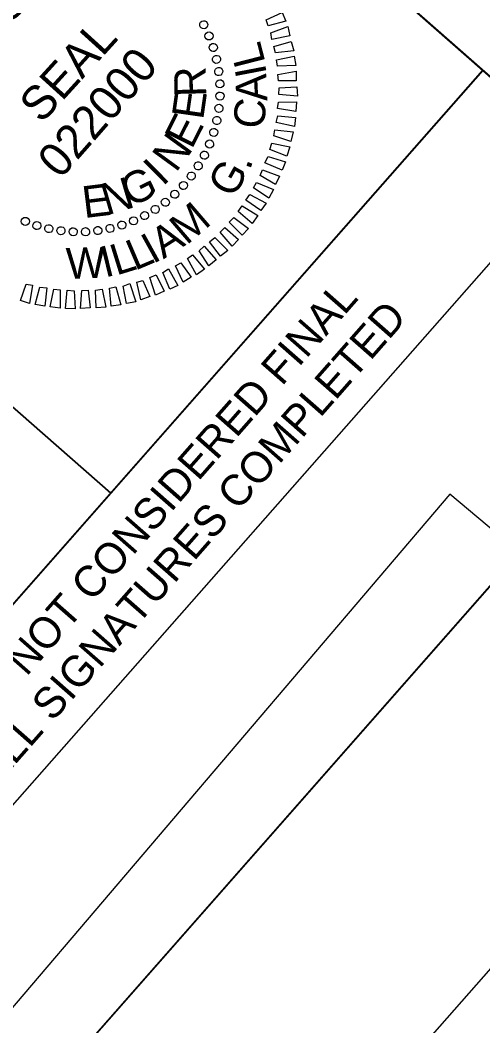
# Model space of a CAD drawing. Extents: x 2189835 to 2191772, y 387461 to 389531.
# Drawn here: x 2190982.4 to 2191064.5, y 389152 to 389330.6 of the extents above; entities that cross this region are included whole.
import ezdxf

# ---------------------------------------------------------------- set-up
doc = ezdxf.new("R2010")
doc.units = 0
for name, color, linetype in [('Sheet Clip Boundary CELL', 7, 'Continuous'), ('Sheet Layout Plan Border', 7, 'Continuous'), ('Sheet Plan CELL', 7, 'Continuous'), ('Sheet Plan Layout CELL', 7, 'Continuous'), ('Sheet Professional Seal CELL', 7, 'Continuous'), ('Sheet Sticker Exception Certification CELL', 7, 'Continuous')]:
    doc.layers.add(name, color=color, linetype=linetype)

msp = doc.modelspace()

# ---------------------------------------------------------------- linework, layer by layer
at = {"layer": 'Sheet Clip Boundary CELL'}
msp.add_lwpolyline([(2190233.88, 388250.3), (2190718.45, 387881.26), (2190850.4, 387777.99), (2191678.63, 388725.5), (2191058.62, 389246.4), (2190957.74, 389128.02), (2190818.15, 389247.91), (2190051.03, 388378.47)], close=True, dxfattribs=at)
at = {"layer": 'Sheet Layout Plan Border'}
msp.add_lwpolyline([(2190847.19, 387643.49), (2191771.58, 388694.94), (2191141.84, 389248.59), (2191016.87, 389106.45), (2190858.04, 389246.09), (2190058.62, 388336.78)], close=True, dxfattribs=at)
at = {"layer": 'Sheet Plan CELL'}
msp.add_line((2190913.95, 389320.85), (2190998.42, 389246.61), dxfattribs=at)
for points in [[(2190951.79, 389420.78), (2189961.36, 388294.21), (2190749.93, 387600.92), (2191740.35, 388727.47)], [(2190913.95, 389320.85), (2190979.96, 389395.96), (2191064.47, 389321.68), (2190998.45, 389246.57)], [(2190749.93, 387600.92), (2189961.36, 388294.17), (2190819.67, 389270.52), (2190932.38, 389171.45), (2191064.47, 389321.68), (2191740.35, 388727.47)], [(2190847.89, 389245.71), (2190913.95, 389320.85), (2190998.45, 389246.57), (2190932.38, 389171.45)]]:
    msp.add_lwpolyline(points, close=True, dxfattribs=at)
at = {"layer": 'Sheet Plan Layout CELL'}
for points in [[(2190952.63, 389101.43), (2191110.61, 389281.13), (2190951.8, 389420.79), (2190793.79, 389241.07)], [(2189961.36, 388294.17), (2190749.93, 387600.92), (2191740.34, 388727.46), (2191110.6, 389281.11), (2190952.63, 389101.43), (2190793.79, 389241.07)]]:
    msp.add_lwpolyline(points, close=True, dxfattribs=at)
at = {"layer": 'Sheet Professional Seal CELL'}
for p, q in [((2191014.97, 389329.79), (2191014.97, 389329.79)), ((2191015.89, 389327.79), (2191015.89, 389327.79)), ((2191016.69, 389325.75), (2191016.69, 389325.75)), ((2191017.23, 389323.63), (2191017.23, 389323.63)), ((2191017.65, 389321.46), (2191017.65, 389321.46)), ((2190992.76, 389318.07), (2190992.76, 389318.07)), ((2191017.83, 389319.31), (2191017.83, 389319.31)), ((2191017.87, 389317.08), (2191017.87, 389317.08)), ((2191017.66, 389314.94), (2191017.66, 389314.94)), ((2191017.28, 389312.75), (2191017.28, 389312.75)), ((2191016.74, 389310.63), (2191016.74, 389310.63)), ((2191016.03, 389308.6), (2191016.03, 389308.6)), ((2191015.1, 389306.62), (2191015.1, 389306.62)), ((2191013.95, 389304.7), (2191013.95, 389304.7)), ((2191012.76, 389302.89), (2191012.76, 389302.89)), ((2191011.35, 389301.2), (2191011.35, 389301.2)), ((2191009.78, 389299.64), (2191009.78, 389299.64)), ((2191006.38, 389296.97), (2191006.38, 389296.97)), ((2191008.1, 389298.25), (2191008.1, 389298.25)), ((2190983.28, 389294.8), (2190983.28, 389294.8)), ((2191002.48, 389294.94), (2191002.48, 389294.94)), ((2191004.47, 389295.85), (2191004.47, 389295.85)), ((2190985.31, 389294.08), (2190985.31, 389294.08)), ((2190987.44, 389293.55), (2190987.44, 389293.55)), ((2190989.63, 389293.16), (2190989.63, 389293.16)), ((2190991.77, 389292.95), (2190991.77, 389292.95)), ((2190994, 389292.99), (2190994, 389292.99)), ((2190996.15, 389293.17), (2190996.15, 389293.17)), ((2190998.32, 389293.6), (2190998.32, 389293.6)), ((2191000.44, 389294.13), (2191000.44, 389294.13))]:
    msp.add_line(p, q, dxfattribs=at)
for points in [[(2191026.04, 389330.66), (2191028.86, 389331.98), (2191029.53, 389330.4), (2191026.36, 389329.59)], [(2191026.87, 389328.34), (2191029.84, 389329.46), (2191030.24, 389327.79), (2191027.02, 389327.15)], [(2191027.39, 389325.9), (2191030.44, 389326.81), (2191030.91, 389325.14), (2191027.67, 389324.78)], [(2191027.83, 389323.52), (2191031.01, 389324.19), (2191031.26, 389322.51), (2191028.04, 389322.4)], [(2191028.1, 389320.95), (2191031.33, 389321.52), (2191031.37, 389319.82), (2191028.18, 389319.82)], [(2191028.33, 389318.55), (2191031.44, 389318.76), (2191031.55, 389317.07), (2191028.24, 389317.38)], [(2191028.18, 389316.03), (2191031.41, 389316.07), (2191031.31, 389314.36), (2191028.05, 389314.89)], [(2191028.06, 389313.61), (2191031.2, 389313.32), (2191031.06, 389311.72), (2191027.79, 389312.39)], [(2191027.55, 389311.13), (2191030.8, 389310.75), (2191030.38, 389309.05), (2191027.38, 389310.02)], [(2191027.04, 389308.72), (2191030.2, 389308.08), (2191029.71, 389306.46), (2191026.65, 389307.6)], [(2191026.38, 389306.38), (2191029.42, 389305.45), (2191028.88, 389303.92), (2191025.78, 389305.24)], [(2191025.37, 389304.01), (2191028.38, 389302.9), (2191027.7, 389301.43), (2191024.94, 389302.99)], [(2191024.28, 389301.77), (2191027.34, 389300.49), (2191026.48, 389298.98), (2191023.77, 389300.82)], [(2191023.11, 389299.61), (2191026.04, 389298.1), (2191025.07, 389296.76), (2191022.43, 389298.6)], [(2191021.75, 389297.6), (2191024.52, 389295.91), (2191023.56, 389294.5), (2191021.08, 389296.6)], [(2191020.3, 389295.56), (2191022.91, 389293.6), (2191021.78, 389292.39), (2191019.47, 389294.69)], [(2191018.68, 389293.78), (2191021.12, 389291.64), (2191020, 389290.43), (2191017.85, 389292.91)], [(2191016.92, 389292), (2191019.23, 389289.71), (2191017.92, 389288.67), (2191015.98, 389291.23)], [(2191015.04, 389290.46), (2191017.15, 389288.01), (2191015.87, 389286.94), (2191014.13, 389289.65)], [(2191012.94, 389288.9), (2191015.06, 389286.39), (2191013.64, 389285.37), (2191012.06, 389288.28)], [(2191008.71, 389286.42), (2191010.33, 389283.48), (2191008.95, 389282.83), (2191007.69, 389285.79)], [(2191010.87, 389287.52), (2191012.71, 389284.92), (2191011.31, 389284.08), (2191009.92, 389286.96)], [(2191004.14, 389284.38), (2191005.39, 389281.49), (2191003.76, 389280.92), (2191003.06, 389284.06)], [(2191006.52, 389285.36), (2191007.91, 389282.47), (2191006.37, 389281.77), (2191005.38, 389284.89)], [(2190984.56, 389283.51), (2190984.04, 389280.25), (2190982.44, 389280.78), (2190983.45, 389283.68)], [(2190987.08, 389283.04), (2190986.76, 389279.79), (2190985.01, 389280.07), (2190985.86, 389283.17)], [(2190989.47, 389282.67), (2190989.44, 389279.44), (2190987.72, 389279.68), (2190988.36, 389282.84)], [(2190991.93, 389282.51), (2190992.11, 389279.3), (2190990.4, 389279.4), (2190990.72, 389282.64)], [(2190994.44, 389282.64), (2190994.79, 389279.48), (2190993.1, 389279.36), (2190993.34, 389282.6)], [(2190996.94, 389282.84), (2190997.55, 389279.59), (2190995.85, 389279.47), (2190995.75, 389282.62)], [(2190999.36, 389283.25), (2191000.21, 389280.05), (2190998.52, 389279.79), (2190998.2, 389283)], [(2191001.84, 389283.81), (2191002.87, 389280.58), (2191001.22, 389280.29), (2191000.66, 389283.37)]]:
    msp.add_lwpolyline(points, close=True, dxfattribs=at)
for centre, major_axis in [((2191014.94, 389329.77), (0.637, 0.336)), ((2191015.88, 389327.79), (0.664, 0.279)), ((2191016.64, 389325.74), (0.686, 0.22)), ((2191017.21, 389323.63), (0.702, 0.16)), ((2191017.6, 389321.47), (0.713, 0.098)), ((2191017.81, 389319.29), (0.719, 0.035)), ((2191017.82, 389317.11), (0.719, -0.028)), ((2191017.64, 389314.93), (0.714, -0.09)), ((2191017.27, 389312.77), (0.704, -0.152)), ((2191016.72, 389310.65), (0.688, -0.213)), ((2191015.98, 389308.59), (0.667, -0.272)), ((2191015.06, 389306.61), (0.64, -0.329)), ((2191013.98, 389304.7), (0.609, -0.384)), ((2191012.73, 389302.91), (0.574, -0.435)), ((2191011.34, 389301.22), (0.533, -0.484)), ((2191009.8, 389299.67), (0.489, -0.528)), ((2191008.13, 389298.25), (0.441, -0.569)), ((2191004.45, 389295.88), (0.336, -0.637)), ((2191006.34, 389296.99), (0.39, -0.605)), ((2190983.28, 389294.85), (-0.272, -0.667)), ((2190985.34, 389294.11), (-0.213, -0.688)), ((2191000.42, 389294.19), (0.22, -0.686)), ((2191002.48, 389294.95), (0.279, -0.664)), ((2190987.46, 389293.56), (-0.152, -0.704)), ((2190989.61, 389293.19), (-0.09, -0.714)), ((2190991.79, 389293.01), (-0.028, -0.719)), ((2190993.98, 389293.02), (0.035, -0.719)), ((2190996.16, 389293.22), (0.098, -0.713)), ((2190998.31, 389293.61), (0.16, -0.702))]:
    msp.add_ellipse(centre, major_axis=major_axis, ratio=0.999708, dxfattribs=at)
at = {"layer": 'Sheet Sticker Exception Certification CELL'}
for p, q in [((2190932.38, 389171.45), (2191064.46, 389321.69)), ((2191082.11, 389306.17), (2190950.03, 389155.94))]:
    msp.add_line(p, q, dxfattribs=at)

# ---------------------------------------------------------------- texts
at = {"layer": 'Sheet Professional Seal CELL'}
for s, height, rotation, p in [('S', 5.64, 46.7018, (2190980.57, 389329.8)), ('SEAL', 5.998, 47.8014, (2190986.17, 389312.07)), ('022000', 5.998, 48.8014, (2190989.5, 389302.2)), ('L', 5.5, 104.4015, (2191025.91, 389323.09)), ('R', 5.64, 91.2828, (2191015.4, 389316.99)), ('I', 5.5, 100.8811, (2191026.16, 389321.05)), ('A', 5.5, 92.6953, (2191026.24, 389316.26)), ('E', 5.64, 81.9255, (2191014.83, 389312.77)), ('C', 5.5, 83.8226, (2191025.56, 389311.12)), ('E', 5.64, 63.2131, (2191012.81, 389307.5)), ('N', 5.64, 53.8578, (2191010, 389303.38)), ('I', 5.64, 44.5026, (2191007.68, 389300.95)), ('G', 5.64, 25.7916, (2191001.93, 389297.28)), ('G', 5.5, 60.7106, (2191020.2, 389298.8)), ('.', 5.5, 70.6423, (2191023.11, 389303.82)), ('N', 5.64, 16.4353, (2190997.74, 389295.9)), ('E', 5.64, 7.0783, (2190993.73, 389295.42)), ('M', 5.5, 40.5895, (2191011.9, 389290.53)), ('A', 5.5, 32.4037, (2191007.78, 389288.09)), ('L', 5.5, 23.0731, (2191002.72, 389286.05)), ('I', 5.5, 28.8833, (2191005.91, 389287.22)), ('W', 5.5, 2.1363, (2190990.62, 389284.6)), ('I', 5.5, 13.7424, (2190997.4, 389284.86)), ('L', 5.5, 17.2629, (2190999.43, 389285.21))]:
    msp.add_text(s, height=height, rotation=rotation, dxfattribs=at).set_placement(p)
at = {"layer": 'Sheet Sticker Exception Certification CELL'}
for s, p in [('DOCUMENT NOT CONSIDERED FINAL', (2190954.07, 389180.45)), ('UNLESS ALL SIGNATURES COMPLETED', (2190957.33, 389170.83))]:
    msp.add_text(s, height=5.5, rotation=48.6794, dxfattribs=at).set_placement(p)

doc.saveas('drawing.dxf')
